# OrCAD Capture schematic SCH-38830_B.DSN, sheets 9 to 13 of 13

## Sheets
9 09 FLEXSPI FLASH: size C
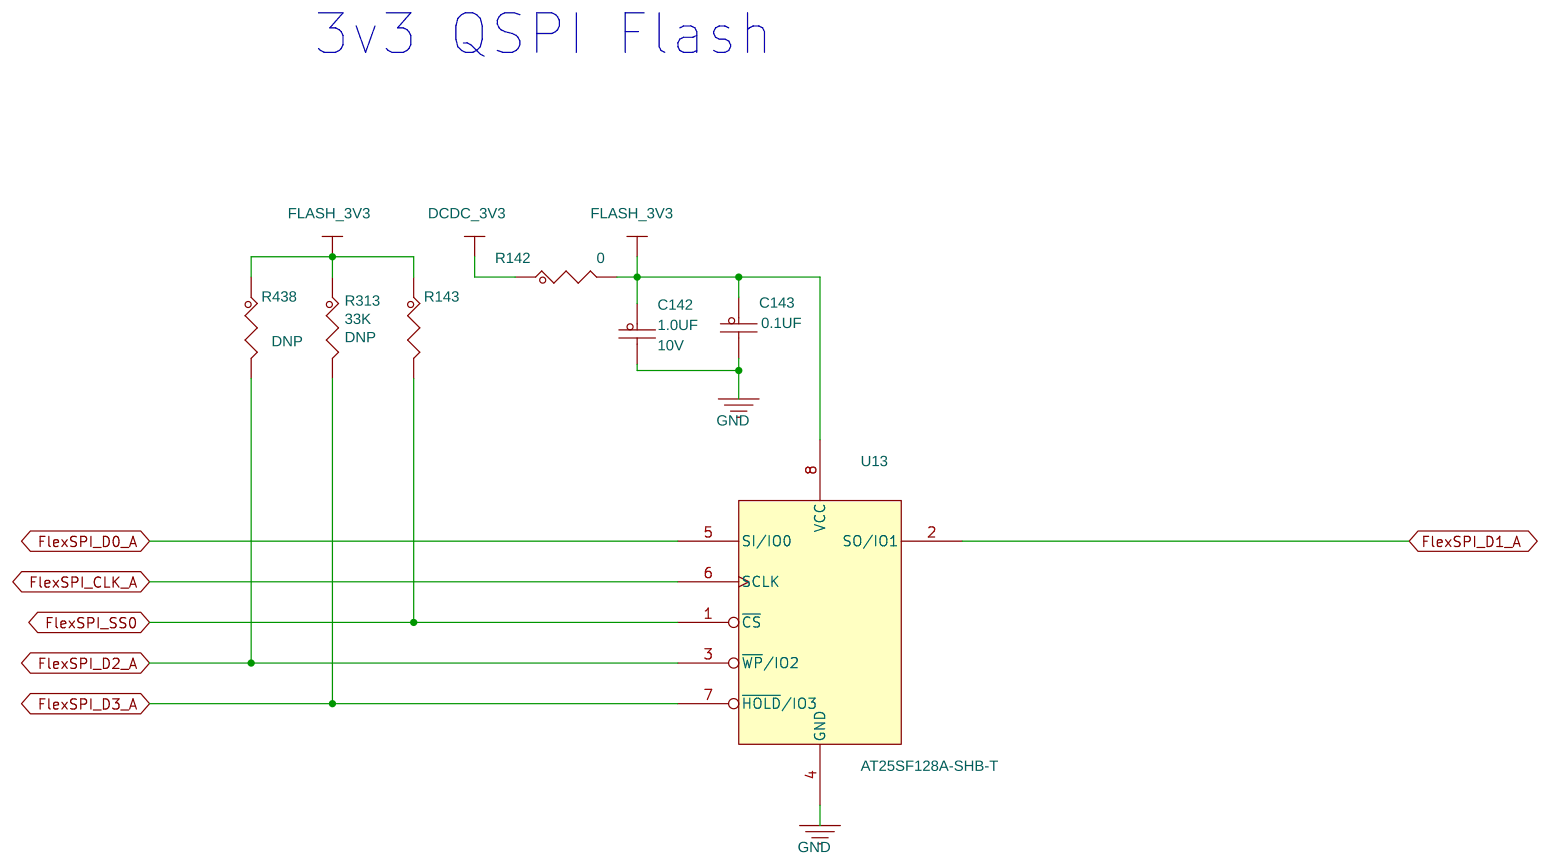
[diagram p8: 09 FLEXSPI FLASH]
10 11 FREELINK: size D; title: MIMXRT1020-EVK
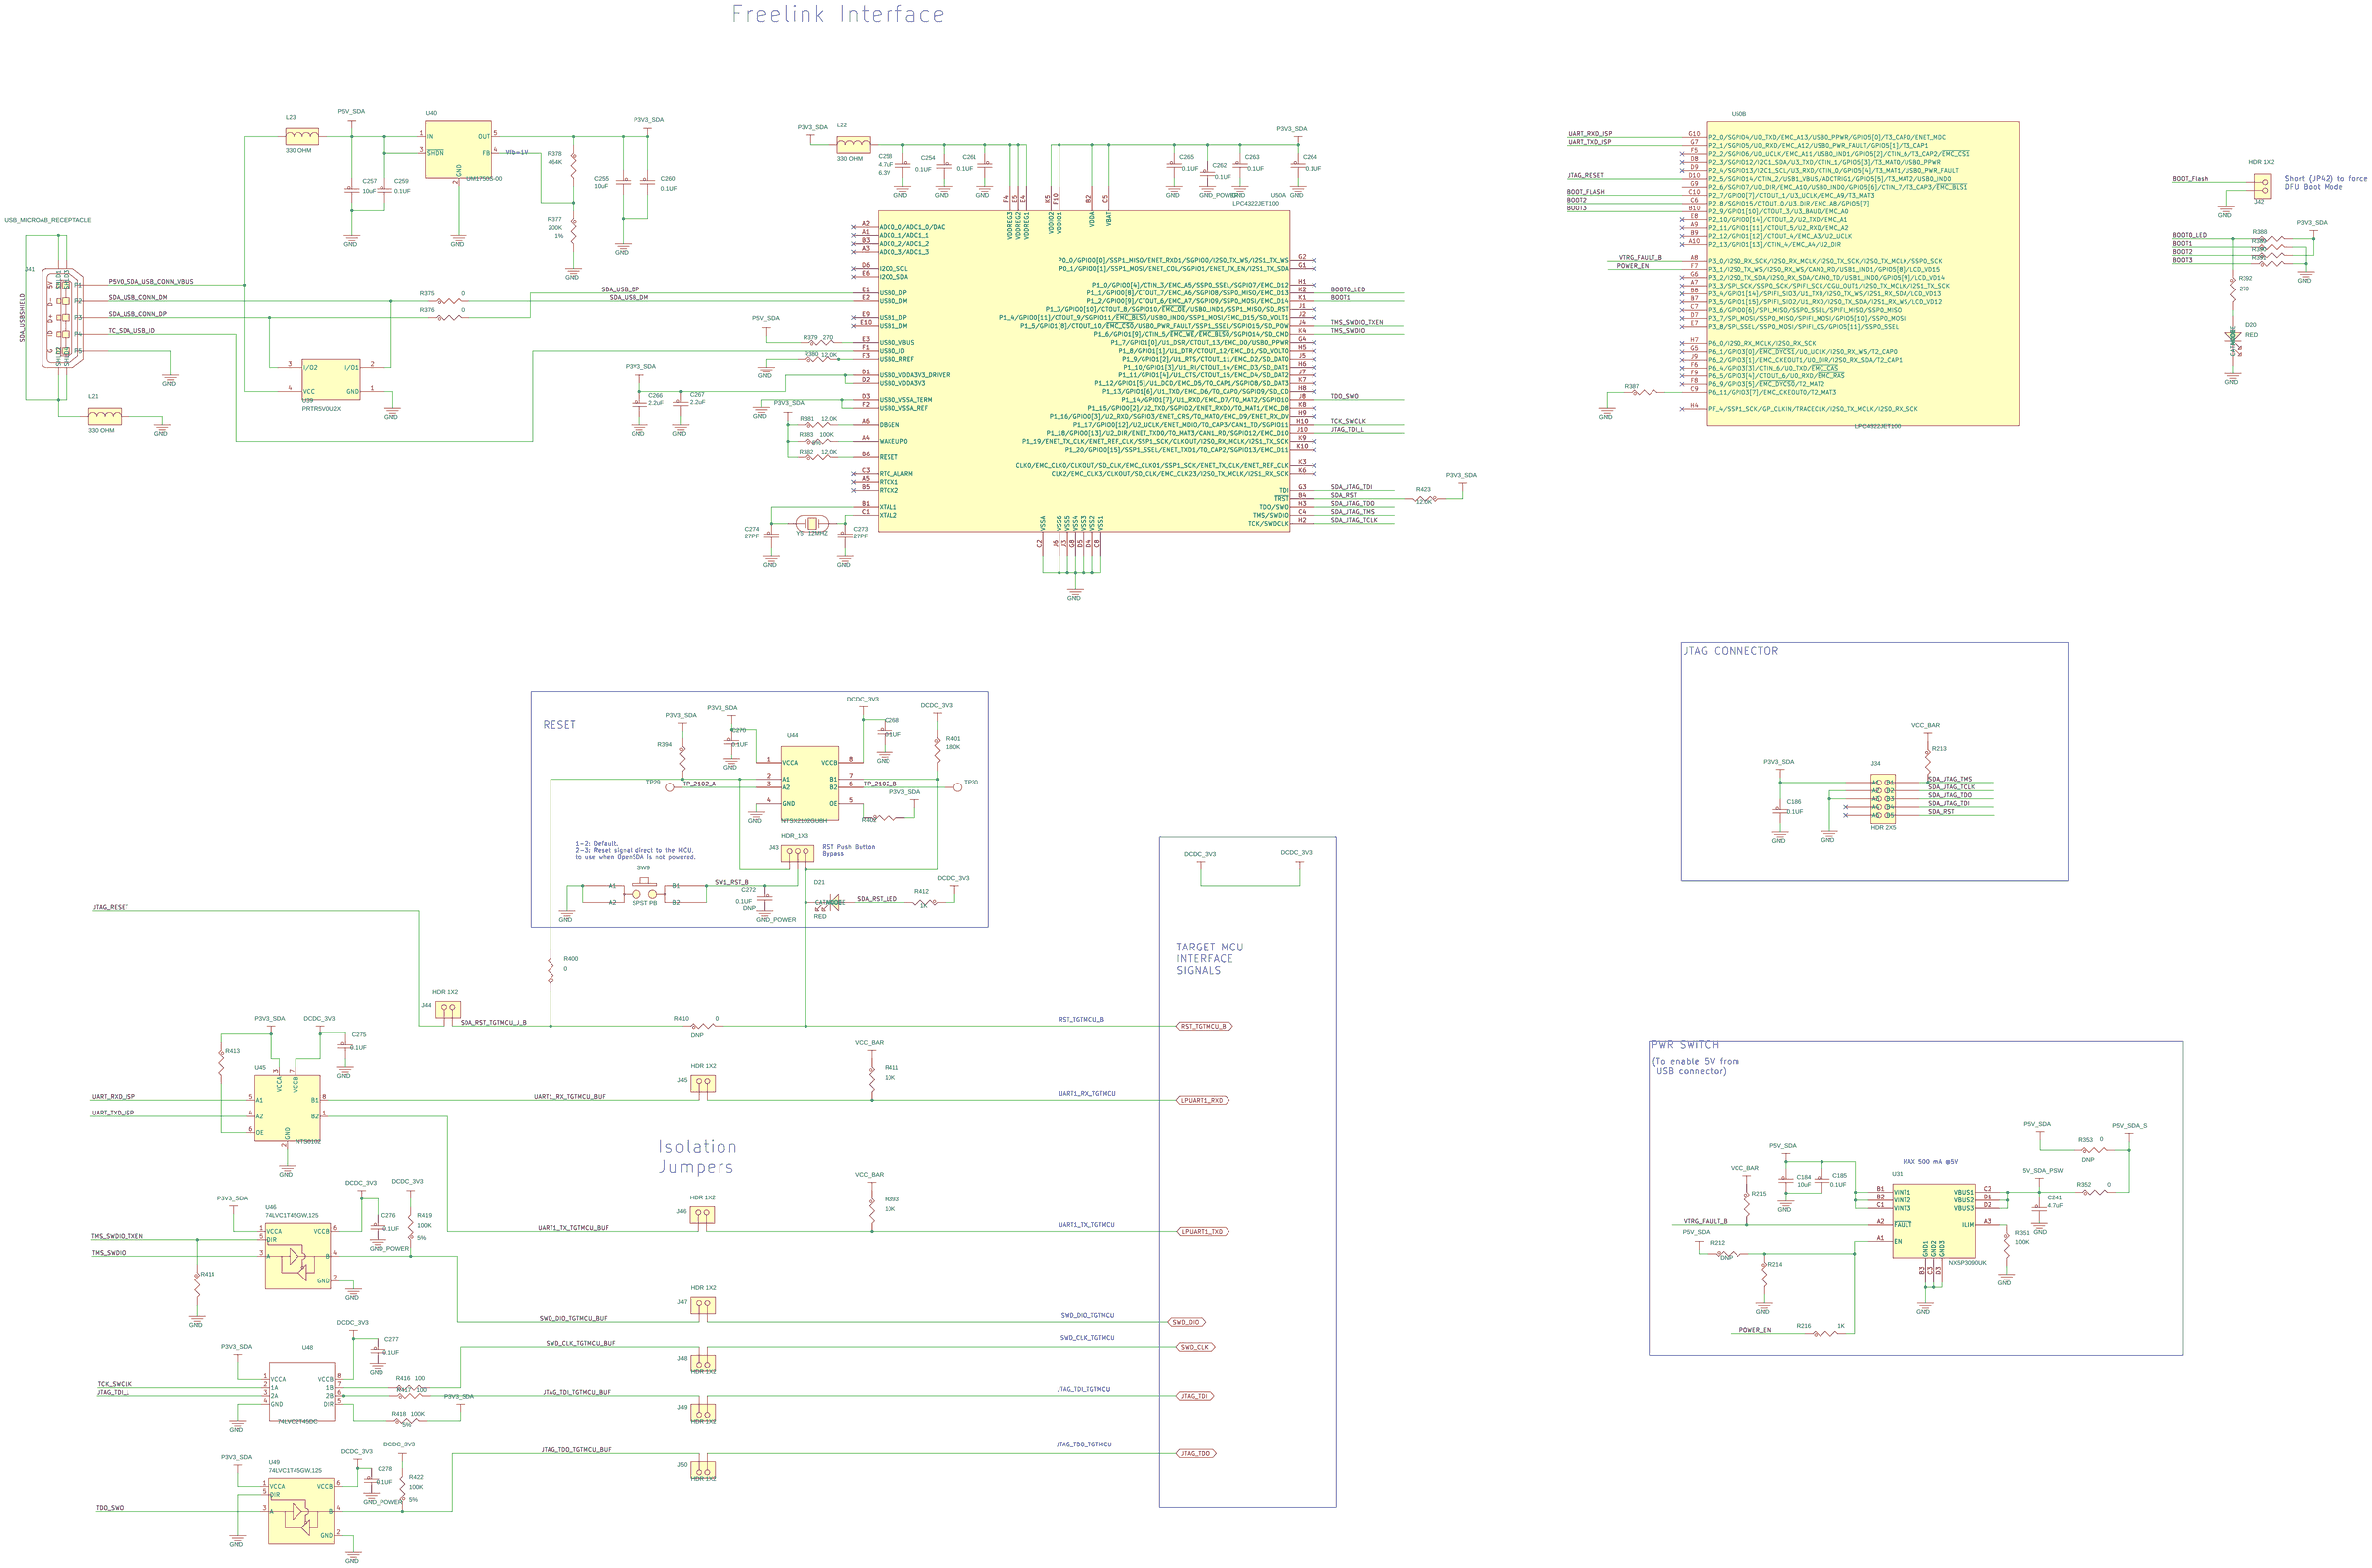
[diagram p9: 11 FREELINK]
11 12 BOOT: size C; title: MIMXRT1020-EVK
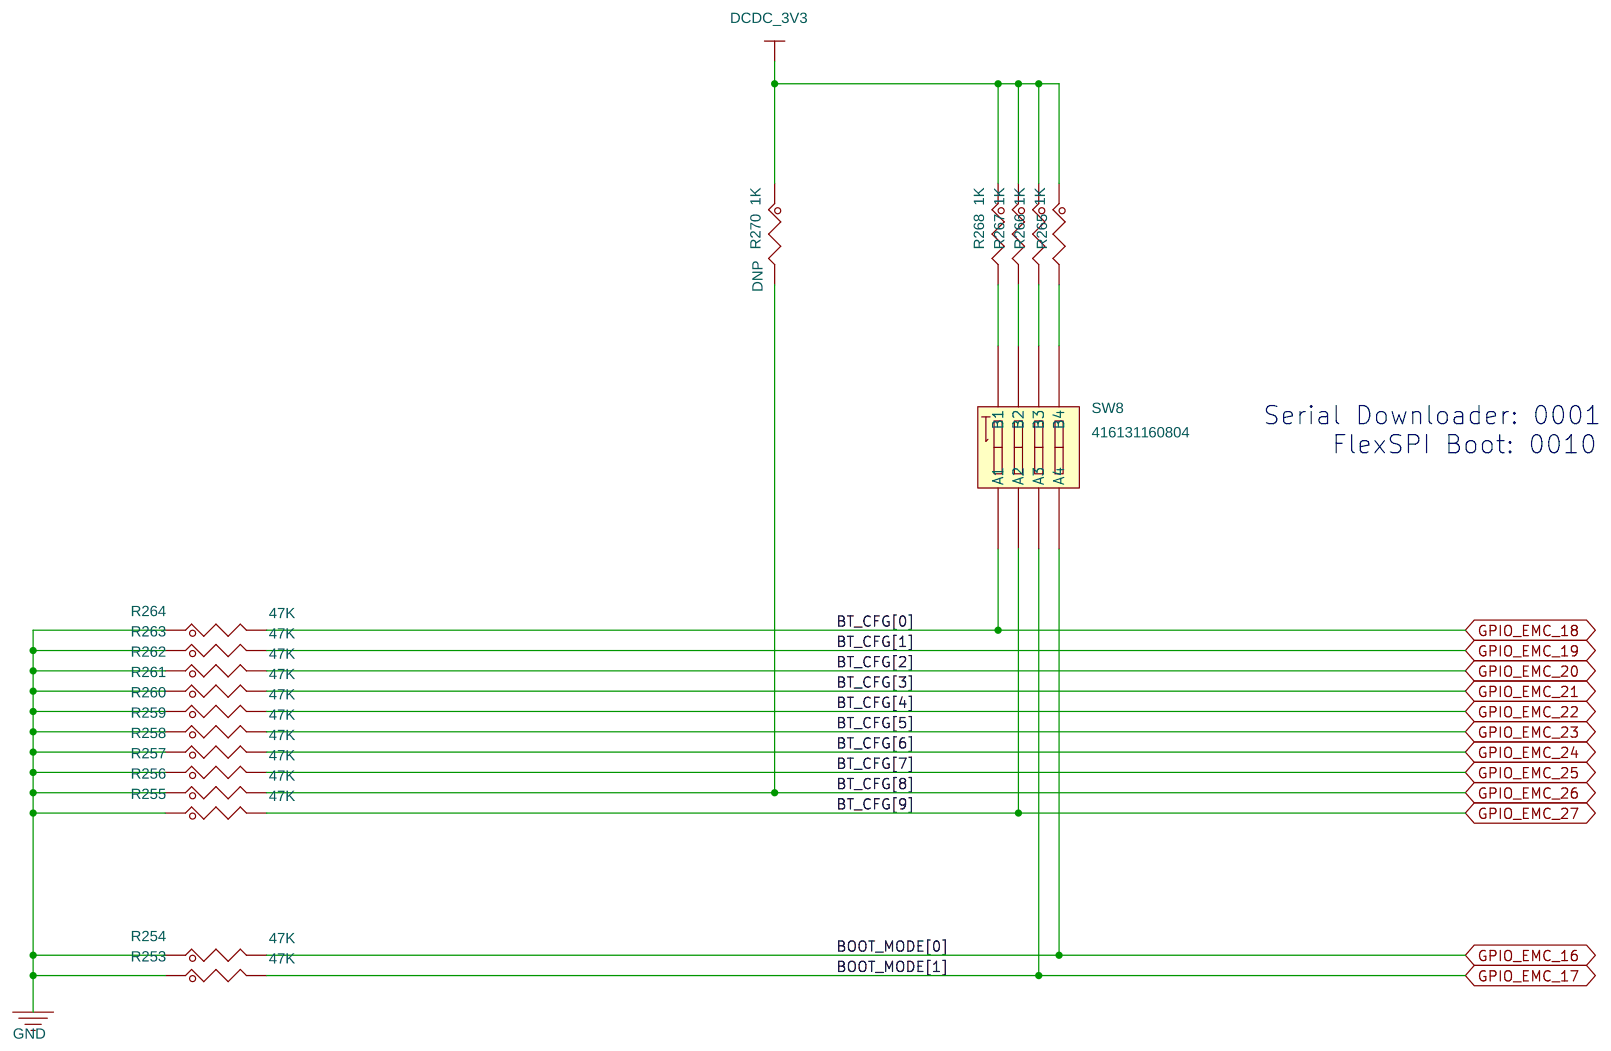
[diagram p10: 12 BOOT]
12 13 MISC: size C; title: MIMXRT1020-EVK
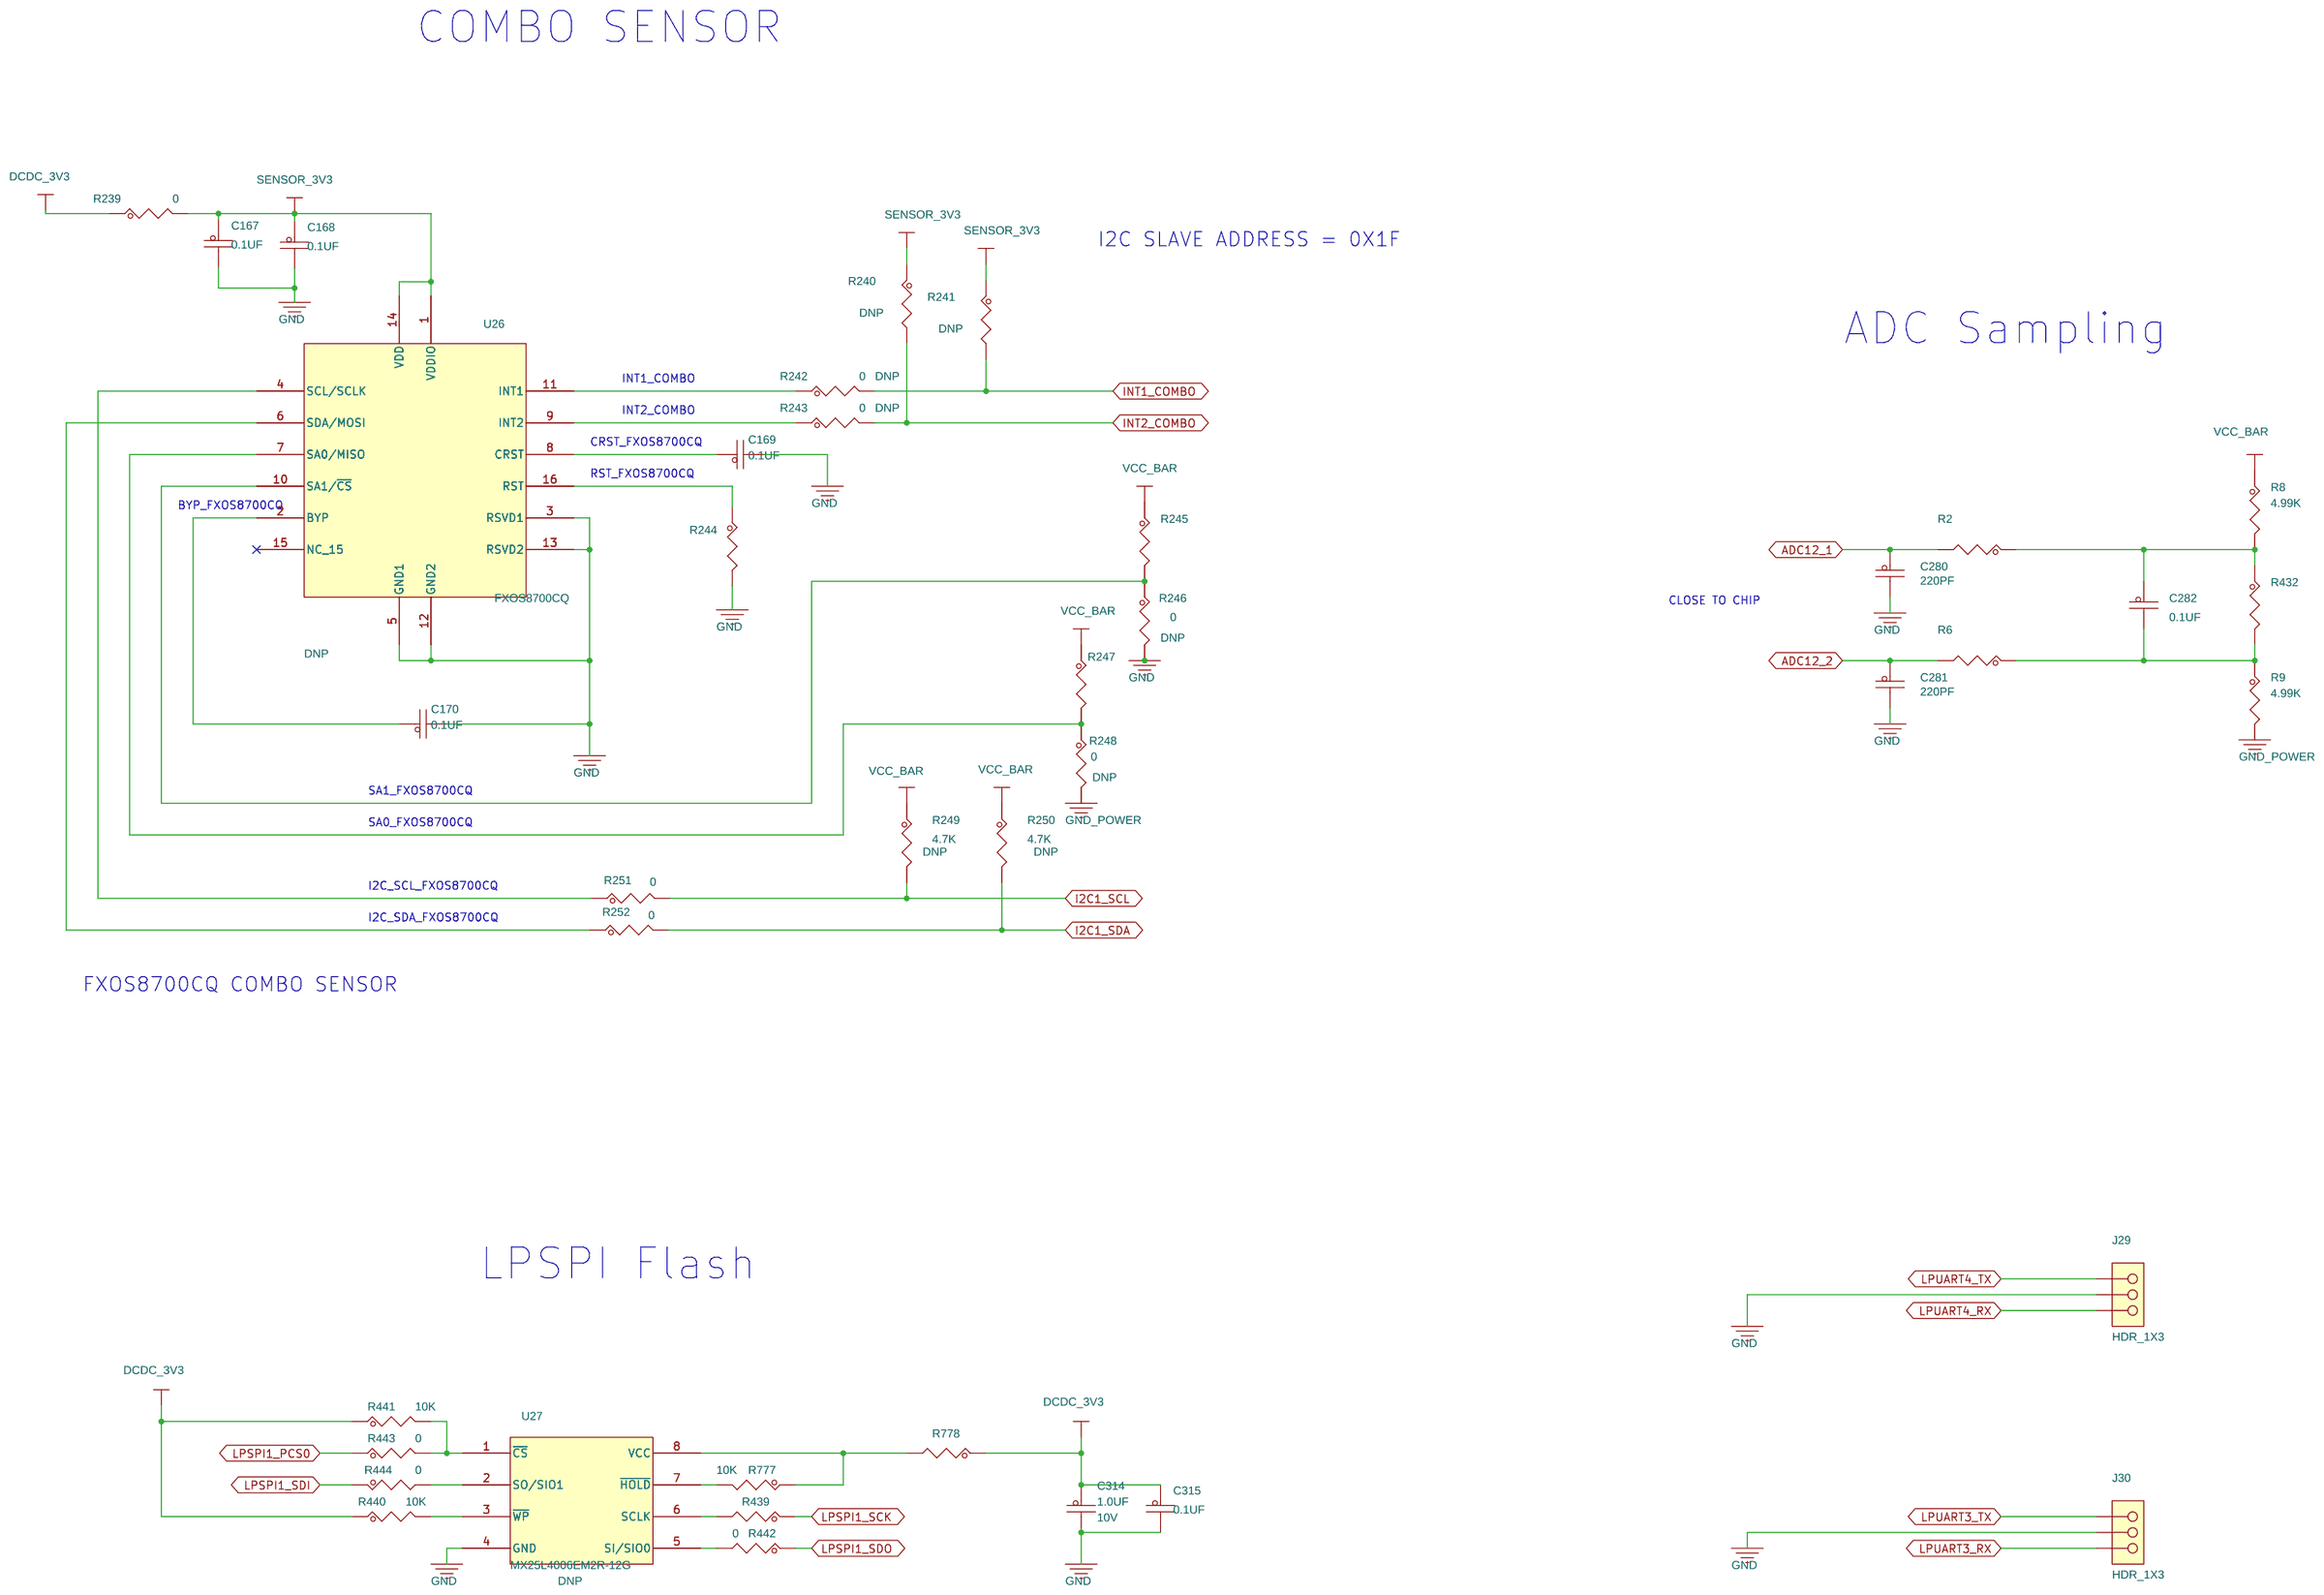
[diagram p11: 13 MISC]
13 10 ARDUINO/JTAG: size C; title: MIMXRT1020-EVK
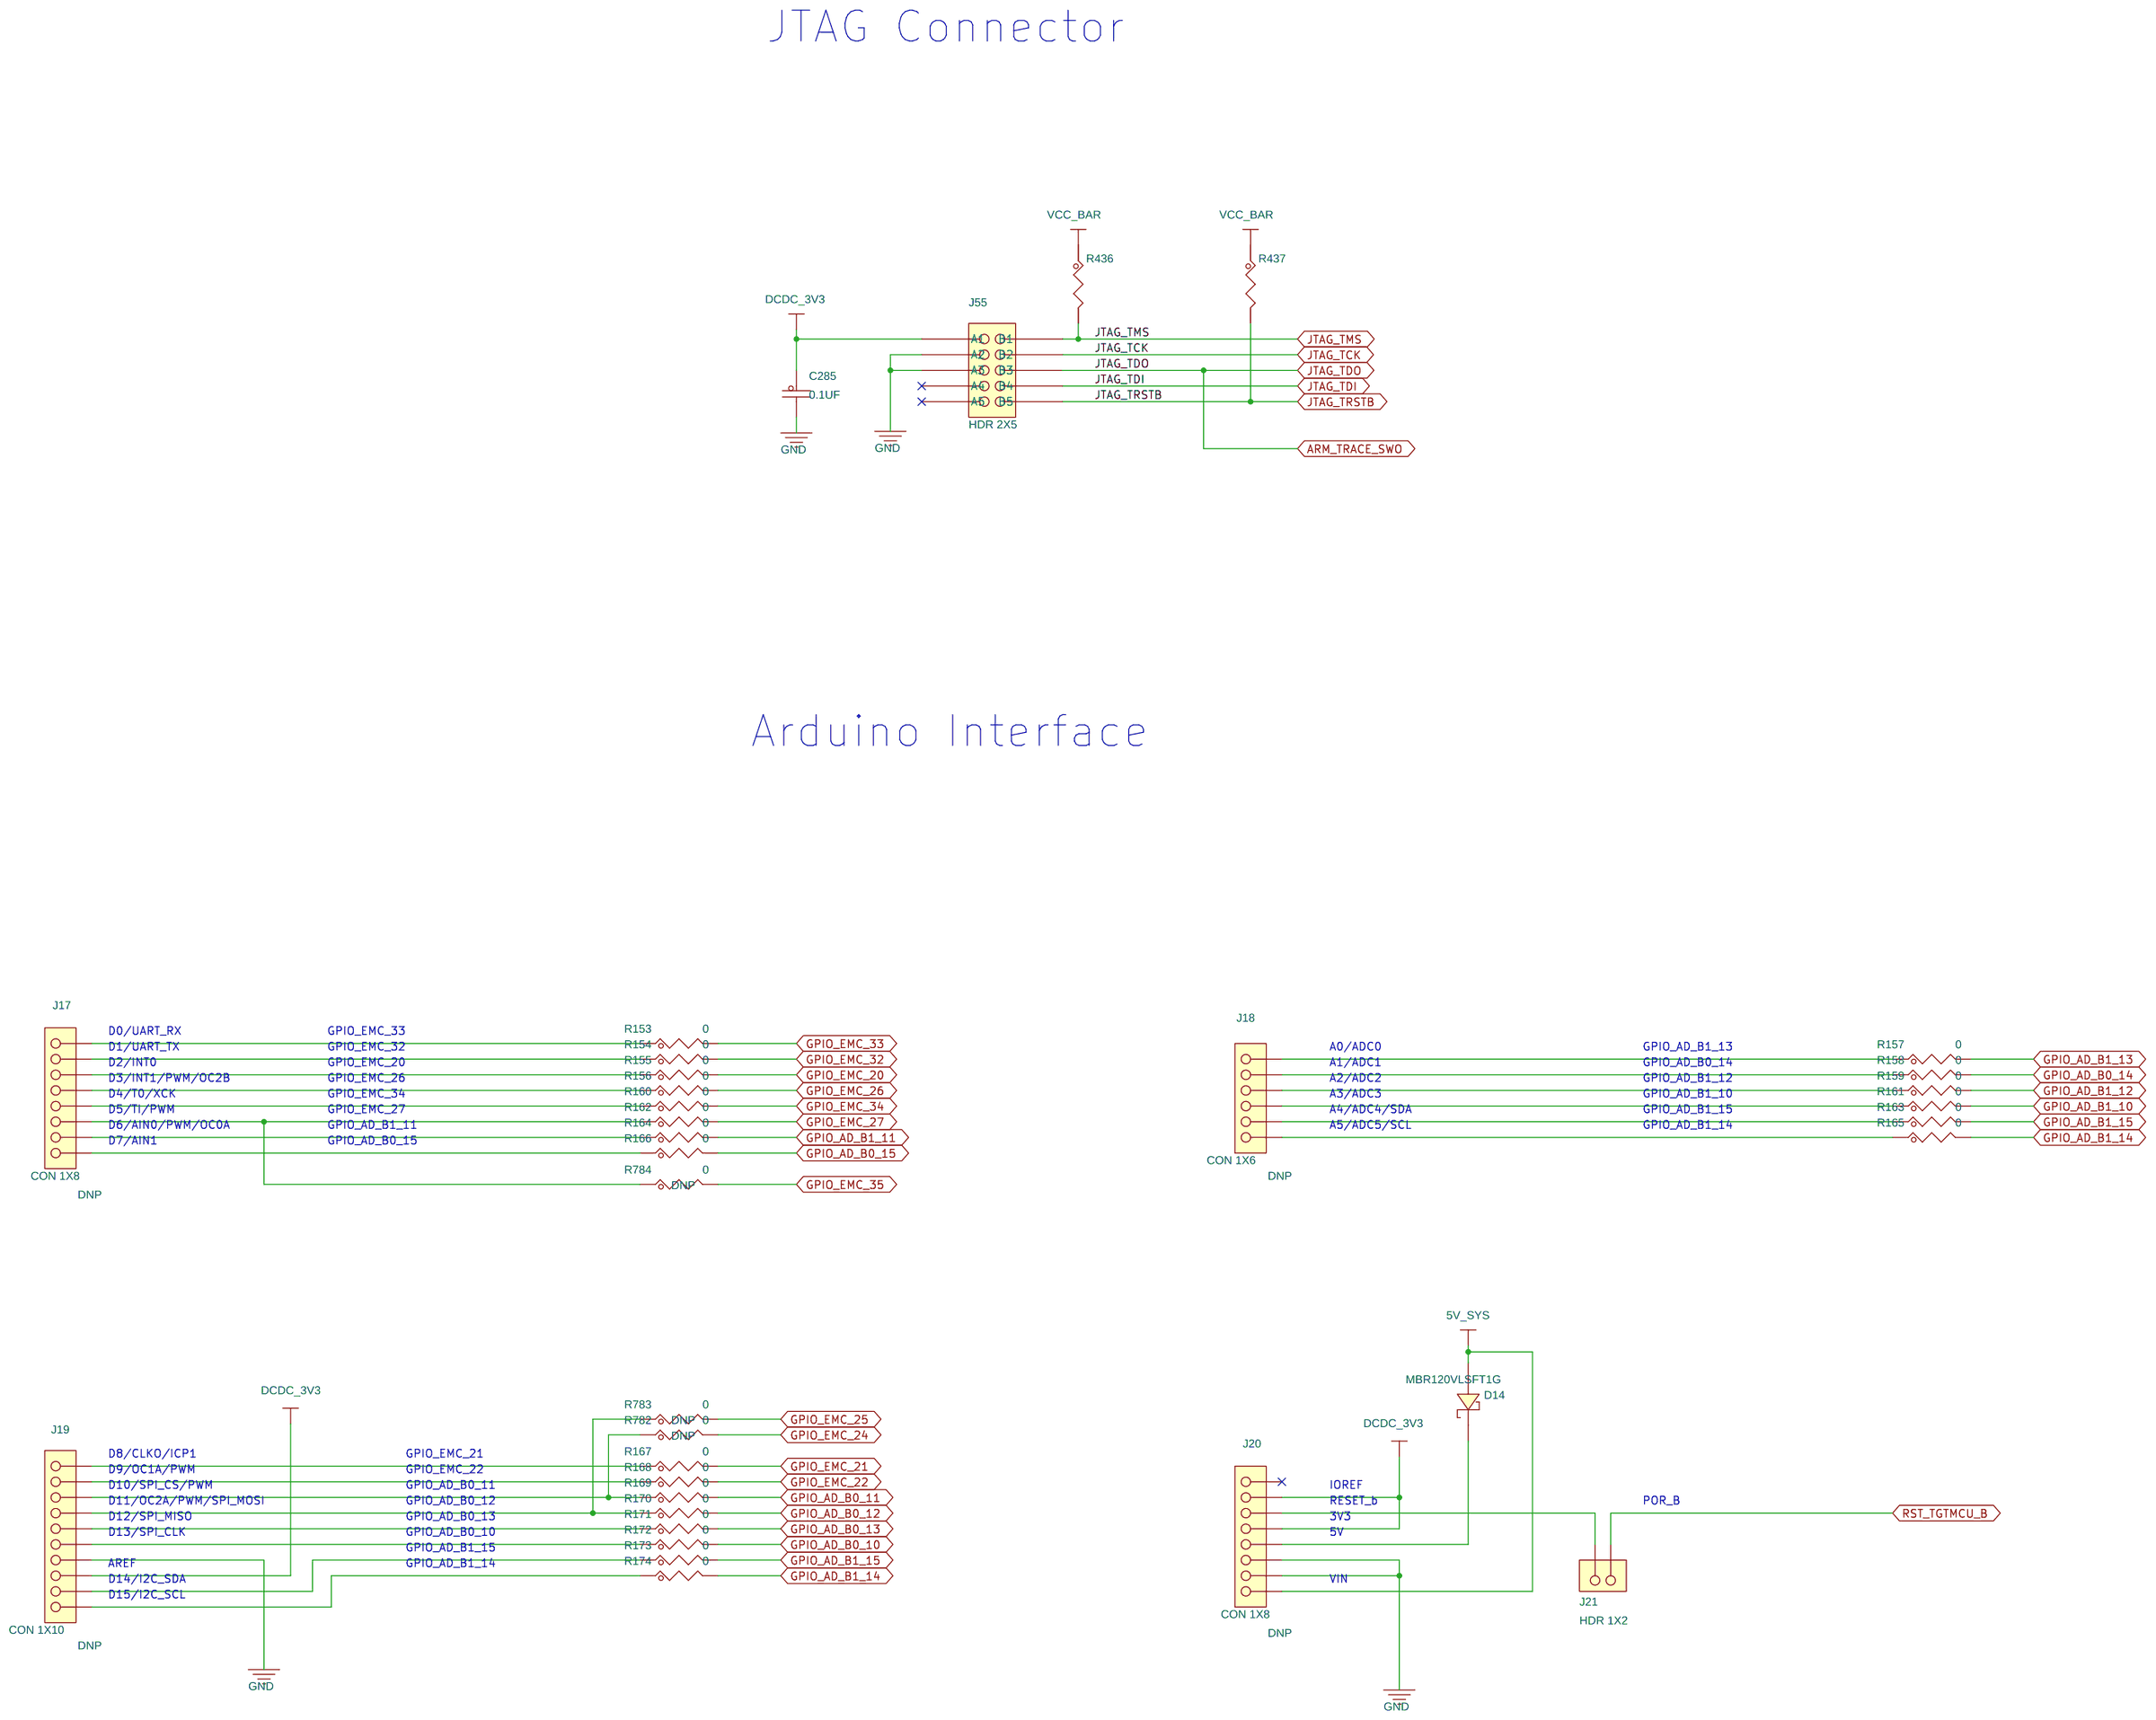
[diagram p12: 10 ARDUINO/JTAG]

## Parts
sheet 09 FLEXSPI FLASH
C142  1.0UF  [0402_CC]
C143  0.1UF  [CC0402_25]
R142  0  [0402_CC]
R143  10K  [0402_CC]
R313  33K  [RC0402_25]
R438  10K  [0402_CC]
U13  AT25SF128A-SHB-T  [SO8-25X75-200]
sheet 10 ARDUINO/JTAG
C285  0.1UF  [CC0402_25]
D14  MBR120VLSFT1G  [SOD-123]
J17  CON 1X8  [con_skt1x8_th]
J18  CON 1X6  [con_skt1x6_th]
J19  CON 1X10  [con_skt1x10_th]
J20  CON 1X8  [con_skt1x8_th]
J21  HDR 1X2  [HDR102]
J55  HDR 2X5  [hdr205_50_th]
R153  0  [0402_CC]
R154  0  [0402_CC]
R155  0  [0402_CC]
R156  0  [0402_CC]
R157  0  [0402_CC]
R158  0  [0402_CC]
R159  0  [0402_CC]
R160  0  [0402_CC]
R161  0  [0402_CC]
R162  0  [0402_CC]
R163  0  [0402_CC]
R164  0  [0402_CC]
R165  0  [0402_CC]
R166  0  [0402_CC]
R167  0  [0402_CC]
R168  0  [0402_CC]
R169  0  [0402_CC]
R170  0  [0402_CC]
R171  0  [0402_CC]
R172  0  [0402_CC]
R173  0  [0402_CC]
R174  0  [0402_CC]
R436  10K  [0402_CC]
R437  10K  [0402_CC]
R782  0  [0402_CC]
R783  0  [0402_CC]
R784  0  [0402_CC]
sheet 11 FREELINK
C184  10uF  [CC0603_OV]
C185  0.1UF  [CC0402_25]
C186  0.1UF  [CC0402_25]
C241  4.7uF  [0402_CC]
C254  0.1UF  [CC0402_25]
C255  10uF  [CC0603_OV]
C257  10uF  [CC0603_OV]
C258  4.7uF  [0402_CC]
C259  0.1UF  [CC0402_25]
C260  0.1UF  [CC0402_25]
C261  0.1UF  [CC0402_25]
C262  0.1UF  [CC0402_25]
C263  0.1UF  [CC0402_25]
C264  0.1UF  [CC0402_25]
C265  0.1UF  [CC0402_25]
C266  2.2uF  [CC0402_25]
C267  2.2uF  [CC0402_25]
C268  0.1UF  [CC0402_25]
C270  0.1UF  [CC0402_25]
C272  0.1UF  [CC0402_25]
C273  27PF  [CC0402_25]
C274  27PF  [CC0402_25]
C275  0.1UF  [CC0402_25]
C276  0.1UF  [CC0402_25]
C277  0.1UF  [CC0402_25]
C278  0.1UF  [CC0402_25]
D20  RED  [LED_0603]
D21  RED  [LED_0603]
J34  HDR 2X5  [hdr205_50_th]
J41  USB_MICROAB_RECEPTACLE  [con_usb5_microab_0p65_sm]
J42  HDR 1X2  [HDR102]
J43  HDR_1X3  [HDR103]
J44  HDR 1X2  [HDR102]
J45  HDR 1X2  [HDR102]
J46  HDR 1X2  [HDR102]
J47  HDR 1X2  [HDR102]
J48  HDR 1X2  [HDR102]
J49  HDR 1X2  [HDR102]
J50  HDR 1X2  [HDR102]
L21  330 OHM  [ind_1608]
L22  330 OHM  [ind_1608]
L23  330 OHM  [ind_1608]
R212  10K  [0402_CC]
R213  10K  [0402_CC]
R214  15K  [RC0402_25]
R215  10K  [0402_CC]
R216  1K  [0402_CC]
R351  100K  [RC0402_25]
R352  0  [0402_CC]
R353  0  [0402_CC]
R375  0  [0402_CC]
R376  0  [0402_CC]
R377  200K  [0402_CC]
R378  464K  [0402_CC]
R379  270  [RC0402_25]
R380  12.0K  [RC0402_25]
R381  12.0K  [RC0402_25]
R382  12.0K  [RC0402_25]
R383  100K  [0402_CC]
R387  2.2K  [RC0402_25]
R388  2.2K  [RC0402_25]
R389  2.2K  [RC0402_25]
R390  2.2K  [RC0402_25]
R391  2.2K  [RC0402_25]
R392  270  [RC0402_25]
R393  10K  [0402_CC]
R394  10K  [0402_CC]
R400  0  [0402_CC]
R401  180K  [RC0402_25]
R402  4.7K  [RC0402_25]
R410  0  [0402_CC]
R411  10K  [0402_CC]
R412  1K  [0402_CC]
R413  4.7K  [RC0402_25]
R414  2.2K  [RC0402_25]
R416  100  [RC0402_25]
R417  100  [RC0402_25]
R418  100K  [0402_CC]
R419  100K  [0402_CC]
R422  100K  [0402_CC]
R423  12.0K  [RC0402_25]
SW9  SPST PB  [SW4_PB_ESW_SM_P177]
TP29  TPAD_030  [TPAD_030]
TP30  TPAD_030  [TPAD_030]
U31  NX5P3090UK  [wlcsp12_0p4_1p38x1p68mm_smdp]
U39  PRTR5V0U2X  [SOT143B]
U40  UM1750S-00  [sot23-5_a]
U44  NTSX2102GU8H  [xqfn8_1p45x1p25mm]
U45  NTS0102  [tssop8_a]
U46  74LVC1T45GW,125  [SOT-363_0P65_SMT]
U48  74LVC2T45DC  [SSOP8_DCU]
U49  74LVC1T45GW,125  [SOT-363_0P65_SMT]
U50  LPC4322JET100  [fbga100_0p8_9x9]  (sections A,B)
Y5  12MHZ  [xtl2_11p6x4p85_sm]
sheet 12 BOOT
R253  47K  [RC0402_25]
R254  47K  [RC0402_25]
R255  47K  [RC0402_25]
R256  47K  [RC0402_25]
R257  47K  [RC0402_25]
R258  47K  [RC0402_25]
R259  47K  [RC0402_25]
R260  47K  [RC0402_25]
R261  47K  [RC0402_25]
R262  47K  [RC0402_25]
R263  47K  [RC0402_25]
R264  47K  [RC0402_25]
R265  1K  [RC0402_25]
R266  1K  [RC0402_25]
R267  1K  [RC0402_25]
R268  1K  [RC0402_25]
R270  1K  [RC0402_25]
SW8  416131160804  [sw4_dip_1p27_6p3x5p7]
sheet 13 MISC
C167  0.1UF  [CC0402_25]
C168  0.1UF  [CC0402_25]
C169  0.1UF  [CC0402_25]
C170  0.1UF  [CC0402_25]
C280  220PF  [CC0402_25]
C281  220PF  [CC0402_25]
C282  0.1UF  [CC0402_25]
C314  1.0UF  [0402_CC]
C315  0.1UF  [0402_CC]
J29  HDR_1X3  [HDR103]
J30  HDR_1X3  [HDR103]
R2  100  [RC0402_25]
R6  100  [RC0402_25]
R8  4.99K  [RC0402_25]
R9  4.99K  [RC0402_25]
R239  0  [0402_CC]
R240  10K  [0402_CC]
R241  10K  [0402_CC]
R242  0  [0402_CC]
R243  0  [0402_CC]
R244  10K  [0402_CC]
R245  10K  [0402_CC]
R246  0  [0402_CC]
R247  10K  [0402_CC]
R248  0  [0402_CC]
R249  4.7K  [RC0402_25]
R250  4.7K  [RC0402_25]
R251  0  [0402_CC]
R252  0  [0402_CC]
R432  10K  [0402_CC]
R439  0  [0402_CC]
R440  10K  [0402_CC]
R441  10K  [0402_CC]
R442  0  [0402_CC]
R443  0  [0402_CC]
R444  0  [0402_CC]
R777  10K  [0402_CC]
R778  0  [0402_CC]
U26  FXOS8700CQ  [QFN5X3_0P5_3X3]
U27  MX25L4006EM2R-12G  [SO8-25X75-200]

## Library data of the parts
C142 C314 = CAP_NP: CAP CER 1.0UF 10V 10% X5R 0402; AGILE_PN: 150-75772; CAD_APPROVED: Yes; FPLIST: CC0402_25,CC0402_HD,0402_CC; HEIGHT: 0.6MM; MFG_NAME01: YAGEO AMERICA; MFG_PN01: CC0402KRX5R6BB105; ROHS: Yes; VOLTAGE: 10V; voltage rating: 10V
C143 C167-C170 C185 C186 C254 C259-C265 C268 C270 C275-C278 C282 C285 C315 = CAP_NP: CAP CER 0.1UF 10V 10% X5R 0402; AGILE_PN: 150-75634; CAD_APPROVED: Yes; FPLIST: CC0402_25,CC0402_HD,0402_CC; HEIGHT: 0.64MM; MFG_NAME01: YAGEO AMERICA; MFG_PN01: CC0402KRX5R6BB104; ROHS: Yes; Tolerance: 10%; VOLTAGE: 10V
R142 R153-R174 R239 R251 R252 R352 R375 R376 R400 R439 R442-R444 R778 = RES: RES MF ZERO OHM 1/16W 5% 0402; AGILE_PN: 470-75394; CAD_APPROVED: Yes; FPLIST: RC0402_25,RC0402_HD,RC0402_X2,0402_CC; HEIGHT: 0.45 MM; MFG_NAME01: ROHM; MFG_PN01: MCR01MZPJ000; ROHS: Yes; Tolerance: 5%
R143 R213 R215 R394 R436 R437 = RES: RES MF 10K 1/16W 5% 0402; AGILE_PN: 470-75557; CAD_APPROVED: Yes; FPLIST: RC0402_25,RC0402_HD,0402_CC; HEIGHT: 0.4 MM; MFG_NAME01: VISHAY INTERTECHNOLOGY; MFG_PN01: CRCW040210K0JNED; ROHS: Yes; TOL: 5%; Tolerance: 5%
R313 = RES: RES MF 33K  1/16W 1% 0402; AGILE_PN: 470-31004; ASSY_OPT: DNP; CAD_APPROVED: Yes; FPLIST: RC0402_25,RC0402_HD,0402_CC; HEIGHT: 0.40 MM; MFG_NAME01: YAGEO AMERICA; MFG_PN01: RC0402FR-0733KL; ROHS: Yes; Temp_Range: -55°C ~ 155°C; Tolerance: 1%
R438 = RES: RES MF 10K 1/16W 5% 0402; AGILE_PN: 470-75557; ASSY_OPT: DNP; CAD_APPROVED: Yes; FPLIST: RC0402_25,RC0402_HD,0402_CC; HEIGHT: 0.4 MM; MFG_NAME01: VISHAY INTERTECHNOLOGY; MFG_PN01: CRCW040210K0JNED; ROHS: Yes; TOL: 5%; Tolerance: 5%
U13 = AT25SF128A: IC MEM NOR FLASH DUAL/QUAD SPI 128MBIT 133MHZ 2.7-3.6V SOP8; AGILE_PN: TMP-WF-34467; CAD_APPROVED: Yes; HEIGHT: 2.16MM; MFG_NAME01: Adesto Technologies Corporation, Inc; PRE_APN: 342-00805; ROHS: Yes; Temp_Range: -40°C ~ 85°C
D14 = DIODE_SCHTKY: DIODE SCH RECT 1A 20V SMT; AGILE_PN: 480-75997; CAD_APPROVED: Yes; HEIGHT: 1MM; MFG_NAME01: ON SEMICONDUCTOR; ROHS: Yes
J17 J20 = CONN_HDR_8X1: CON 1X8 SKT TH 100MIL SP 343H AU 392L; AGILE_PN: 210-80963; ASSY_OPT: DNP; CAD_APPROVED: Yes; HEIGHT: 8.7MM; MFG_NAME01: Townes Enterprice Co.,Ltd; MFG_PN01: F209-1*08SG1-0A-NH; ROHS: Yes
J18 = CONN_HDR_6X1: CON 1X6 SKT TH 100MIL SP 343H AU 392L; AGILE_PN: 210-80962; ASSY_OPT: DNP; CAD_APPROVED: Yes; HEIGHT: 8.7MM; MFG_NAME01: Townes Enterprice Co.,Ltd; MFG_PN01: F209-1*06SG1-0A-NH; ROHS: Yes
J19 = CONN_HDR_10X1: CON 1X10 SKT TH 100MIL SP 343H AU 392L; AGILE_PN: 210-80964; ASSY_OPT: DNP; CAD_APPROVED: Yes; HEIGHT: 8.7MM; MFG_NAME01: Townes Enterprice Co.,Ltd; MFG_PN01: F209-1*10SG1-0A-NH; ROHS: Yes
J21 J42 J44-J50 = CONN_HDR_2X1: HDR 1X2 TH 100MIL SP 339H AU 98L; AGILE_PN: 210-81490; CAD_APPROVED: Yes; HEIGHT: 8.59MM; MFG_NAME01: ANYTRONIC CORPORATION LIMITED; MFG_PN01: 0901S0202011N9T-31RF; ROHS: Yes; Temp_Range: -55°C to +105°C
J34 J55 = CONN_HDR_5X2: HDR 2X5 TH 50MIL CTR 172H AU 91L; AGILE_PN: 210-81466; CAD_APPROVED: Yes; HEIGHT: 4.38MM; MFG_NAME01: ANYTRONIC CORPORATION LIMITED; MFG_PN01: 0922S0205011N9T-31RF; ROHS: Yes; Temp_Range: -55DegC to +105DegC
R242 R243 R246 R248 R353 R410 R782-R784 = RES: RES MF ZERO OHM 1/16W 5% 0402; AGILE_PN: 470-75394; ASSY_OPT: DNP; CAD_APPROVED: Yes; FPLIST: RC0402_25,RC0402_HD,RC0402_X2,0402_CC; HEIGHT: 0.45 MM; MFG_NAME01: ROHM; MFG_PN01: MCR01MZPJ000; ROHS: Yes; Tolerance: 5%
C184 C255 C257 = CAP_NP: CAP CER 10UF 10V 10% X5R 0603; AGILE_PN: 150-78675; CAD_APPROVED: Yes; FPLIST: CC0603_OV,CC0603,0603_CC; HEIGHT: 1.016MM; MFG_NAME01: MURATA; MFG_PN01: GRM188R61A106KE69D; ROHS: Yes; Temp_Range: -55°C ~ 85°C; Tolerance: 10%; VOLTAGE: 10v
C241 = CAP_NP: CAP CER 4.7UF 6.3V 20% X5R 0402; AGILE_PN: 150-78463; CAD_APPROVED: Yes; FPLIST: CC0402_25,CC0402_HD,0402_CC; HEIGHT: 0.65MM; MFG_NAME01: TDK; MFG_PN01: C1005X5R0J475M050BC; ROHS: Yes; TOL: 20%; Tolerance: 20%; VOLTAGE: 6.3V
C258 = CAP_NP: CAP CER 4.7UF 6.3V 20% X5R 0402; AGILE_PN: 150-78463; CAD_APPROVED: Yes; FPLIST: CC0402_25,CC0402_HD,0402_CC; HEIGHT: 0.65MM; MFG_NAME01: TDK; MFG_PN01: C1005X5R0J475M050BC; ROHS: Yes; Tolerance: 20%; VOLTAGE: 6.3V; voltage rating: 6.3V
C266 C267 = CAP_NP: CAP CER 2.2uF 6.3V 10% X5R 0402; AGILE_PN: 150-79454; CAD_APPROVED: Yes; FPLIST: CC0402_25,CC0402_HD,0402_CC; HEIGHT: 0.55MM; MFG_NAME01: MURATA; MFG_PN01: GRM155R60J225KE95; ROHS: Yes; Tolerance: 10%; VOLTAGE: 6.3V
C272 = CAP_NP: CAP CER 0.1UF 10V 10% X5R 0402; AGILE_PN: 150-75634; ASSY_OPT: DNP; CAD_APPROVED: Yes; FPLIST: CC0402_25,CC0402_HD,0402_CC; HEIGHT: 0.64MM; MFG_NAME01: YAGEO AMERICA; MFG_PN01: CC0402KRX5R6BB104; ROHS: Yes; Tolerance: 10%; VOLTAGE: 10V
C273 C274 = CAP_NP: CAP CER 27PF 50V 5% C0G 0402; AGILE_PN: 150-30109; CAD_APPROVED: Yes; FPLIST: CC0402_25,CC0402_HD,0402_CC; HEIGHT: .55mm; MFG_NAME01: KEMET; MFG_PN01: C0402C270J5GAC; ROHS: Yes; Tolerance: 5%; VOLTAGE: 50V
D20 D21 = LED: LED ULTRA BRIGHT RED SGL 30MA 0603; AGILE_PN: 370-75079; CAD_APPROVED: Yes; HEIGHT: 0.9MM; MFG_NAME01: LITE ON; MFG_PN01: LTST-C190KRKT; ROHS: Yes
J41 = USB_MINI_AB_RECEPTACLE: CON 5 USB MICRO_AB RA SKT SMT 0.65MM SP 110H AU; AGILE_PN: 211-80104; CAD_APPROVED: Yes; HEIGHT: 2.8MM; MFG_NAME01: ANYTRONIC CORPORATION LIMITED; MFG_PN01: 23971101#LCP-58RF; ROHS: Yes; Temp_Range: -55&#8451; to 105&#8451;
J29 J30 J43 = CONN_HDR_3X1: HDR 1X3 TH 100MIL SP 338H AU 98L; AGILE_PN: 210-81491; CAD_APPROVED: Yes; HEIGHT: 8.59MM; MFG_NAME01: ANYTRONIC CORPORATION LIMITED; MFG_PN01: 0901S0203011N9T-31RF; ROHS: Yes; Temp_Range: -55°C to +105°C
L21-L23 = BEAD: IND FER BEAD 330OHM@100MHZ 1.7A 0603; AGILE_PN: 180-78156; CAD_APPROVED: Yes; FPLIST: ind_1608,0603_CC; HEIGHT: 0.95MM; MFG_NAME01: TDK; MFG_PN01: MPZ1608S331A; PART_TYPE: FERRITE\BEAD; ROHS: Yes; Tolerance: 25%
R212 R240 R241 = RES: RES MF 10K 1/16W 5% 0402; AGILE_PN: 470-75557; ASSY_OPT: DNP; CAD_APPROVED: Yes; FPLIST: RC0402_25,RC0402_HD,0402_CC; HEIGHT: 0.4 MM; MFG_NAME01: VISHAY INTERTECHNOLOGY; MFG_PN01: CRCW040210K0JNED; ROHS: Yes; Tolerance: 5%
R214 = RES: RES MF 15K  1/16W 1% 0402; AGILE_PN: 470-30965; CAD_APPROVED: Yes; FPLIST: RC0402_25,RC0402_HD,0402_CC; HEIGHT: 0.40 MM; MFG_NAME01: WALSIN TECHNOLOGY CORP.; MFG_PN01: WR04X1502FTL; ROHS: Yes; SIGNAL_MODEL: DEFAULT_RESISTOR_15000OHM_2_1; TOL: 1%; Tolerance: 1%
R216 R265-R268 R412 = RES: RES MF 1.0K 1/16W 5% 0402; AGILE_PN: 470-75555; CAD_APPROVED: Yes; FPLIST: RC0402_25,RC0402_HD,RC0402_X2,0402_CC; HEIGHT: 0.41mm; MFG_NAME01: VISHAY INTERTECHNOLOGY; MFG_PN01: CRCW04021K00JNED; ROHS: Yes; Tolerance: 5%
R351 = RES: RES MF 100K 1/16W 1% 0402; AGILE_PN: 470-76240; CAD_APPROVED: Yes; FPLIST: RC0402_25,RC0402_HD,0402_CC; HEIGHT: 0.4MM; MFG_NAME01: NIC COMPONENTS CORP; MFG_PN01: NRCL04F1003TRF; ROHS: Yes; Tolerance: 1%
R377 = RES: RES MF 200K 1/10W 1% AEC-Q200 0402; AGILE_PN: 470-31093; CAD_APPROVED: Yes; FPLIST: RC0402_25,RC0402_HD,0402_CC; HEIGHT: 0.40 MM; MFG_NAME01: KOA SPEER; MFG_PN01: RK73H1ETTP2003F; ROHS: Yes; Temp_Range: -55C to +155C; Tolerance: 1%
R378 = RES: RES MF 464K 1/10W 1% AEC-Q200 0402; AGILE_PN: 470-31135; CAD_APPROVED: Yes; FPLIST: RC0402_25,RC0402_HD,0402_CC; HEIGHT: 0.40 MM; MFG_NAME01: KOA SPEER; MFG_PN01: RK73H1ETTP4643F; ROHS: Yes; Temp_Range: -55C to +155C; Tolerance: 1%
R379 R392 = RES: RES MF 270 OHM 1/16W 5% 0402; AGILE_PN: 470-81890; CAD_APPROVED: Yes; FPLIST: RC0402_25,RC0402_HD,0402_CC; HEIGHT: 0.4MM; MFG_NAME01: Yageo; MFG_PN01: RC0402JR-07270RL; ROHS: Yes; Temp_Range: -55C to +155C; Tolerance: 5%
R380-R382 R423 = RES: RES MF 12.0K 1/16W 1% 0402; AGILE_PN: 470-76083; CAD_APPROVED: Yes; FPLIST: RC0402_25,RC0402_HD,0402_CC; HEIGHT: 0.4 MM; MFG_NAME01: BOURNS; MFG_PN01: CR0402-FX-1202GLF; ROHS: Yes; Tolerance: 1%
R383 R418 R419 R422 = RES: RES MF 100K 1/16W 5% 0402; AGILE_PN: 470-75597; CAD_APPROVED: Yes; FPLIST: RC0402_25,RC0402_HD,0402_CC; HEIGHT: 0.40 MM; MFG_NAME01: VENKEL COMPANY; MFG_PN01: CR0402-16W-104JT; ROHS: Yes; TOL: 5%; Temp_Range: -55C to +155C; Tolerance: 5%
R387-R391 R414 = RES: RES MF 2.2K 1/16W 5% 0402; AGILE_PN: 470-76602; CAD_APPROVED: Yes; FPLIST: RC0402_25,RC0402_HD,0402_CC; HEIGHT: 0.4 MM; MFG_NAME01: YAGEO AMERICA; MFG_PN01: RC0402JR-072K2L; ROHS: Yes; TOL: 5%; Tolerance: 5%
R244 R245 R247 R393 R411 R432 R440 R441 R777 = RES: RES MF 10K 1/16W 5% 0402; AGILE_PN: 470-75557; CAD_APPROVED: Yes; FPLIST: RC0402_25,RC0402_HD,0402_CC; HEIGHT: 0.4 MM; MFG_NAME01: VISHAY INTERTECHNOLOGY; MFG_PN01: CRCW040210K0JNED; ROHS: Yes; Tolerance: 5%
R401 = RES: RES MF 180K 1/10W 1% AEC-Q200 0402; AGILE_PN: 470-31088; CAD_APPROVED: Yes; FPLIST: RC0402_25,RC0402_HD,0402_CC; HEIGHT: 0.40 MM; MFG_NAME01: KOA SPEER; MFG_PN01: RK73H1ETTP1803F; ROHS: Yes; SIGNAL_MODEL: DEFAULT_RESISTOR_180000OHM_2_1; TOL: 1%; Temp_Range: -55C to +155C; Tolerance: 1%
R402 R413 = RES: RES MF 4.7K 1/16W 5% 0402; AGILE_PN: 470-75626; CAD_APPROVED: Yes; FPLIST: RC0402_25,RC0402_HD,0402_CC; HEIGHT: 0.41mm; MFG_NAME01: NIC COMPONENTS CORP; MFG_PN01: NRCL04J472TRF; ROHS: Yes; SIGNAL_MODEL: DEFAULT_RESISTOR_4700OHM_2_1; TOL: 5%; Tolerance: 5%
R416 R417 = RES: RES MF 100 OHM 1/16W 5% 0402; AGILE_PN: 470-82143; CAD_APPROVED: Yes; FPLIST: RC0402_25,RC0402_HD,RC0402_X2,0402_CC; HEIGHT: 0.45MM; MFG_NAME01: YAGEO AMERICA; MFG_PN01: RC0402JR-07100RL; ROHS: Yes; Temp_Range: -55°C to +155°C; Tolerance: 5%
SW9 = SW_PB_ESW: SW SPST MOM NO PB TACT 50mA 50V SMT; AGILE_PN: 510-77562; CAD_APPROVED: Yes; HEIGHT: 5MM; MFG_NAME01: E SWITCH; MFG_PN01: TL3301AF260QG/TR; ROHS: Yes
TP29 TP30 = TESTLOOP: TEST POINT PAD 30MIL DIA SMT, NO PART TO ORDER; AGILE_PN: 211-76642; CAD_APPROVED: Yes; HEIGHT: 0.1MM; MFG_NAME01: NOTACOMPONENT; MFG_PN01: NOTACOMPONENT; ROHS: Yes
U31 = NX5P3090UK_WLCSP12: IC USB PD TYPE C CURRENT LIMITED PWR SW 2.5-5.5V WLCSP12; AGILE_PN: 312-81574; CAD_APPROVED: Yes; HEIGHT: 0.565 MM; MFG_NAME01: NXP SEMICONDUCTORS; MFG_PN01: NX5P3090UK,012; ROHS: Yes
U39 = PRTR5V0U2X: IC USB ESD PROTECTION 8KV SOT143; AGILE_PN: 315-76725; CAD_APPROVED: Yes; HEIGHT: 1.1MM; MFG_NAME01: NEXPERIA; MFG_PN01: PRTR5V0U2X,215; ROHS: Yes; Temp_Range: -40° C to +85° C
U40 = UM1750S-00_5P: IC VREG LDO ADJ 1-5V 350mA 2.5-6V SOT23-5; AGILE_PN: 315-80554; CAD_APPROVED: Yes; HEIGHT: 1.25MM; MFG_NAME01: Union Semiconductor, Inc; ROHS: Yes
U44 = NTSX2102GU8H_8P: IC DUAL SUPPLY XCVR 50 MBPS 5.5V XQFN8; AGILE_PN: 312-80763; CAD_APPROVED: Yes; HEIGHT: 0.5MM; MFG_NAME01: NXP Semiconductors; ROHS: Yes; VOLTAGE: 5.5V
U45 = NTB0102_8P: IC XCVR 2-BIT 1.65-3.6V/2.3-5.5V TSSOP8; AGILE_PN: 312-80889; CAD_APPROVED: Yes; HEIGHT: 1.1MM; MFG_NAME01: NXP SEMICONDUCTORS; MFG_PN01: NTS0102DP; ROHS: Yes
U46 U49 = 74LVCH1T45_6P: IC XCVR XLATING DUAL 3-STATE 1.2- 5.5V TSSOP6; AGILE_PN: 312-81277; CAD_APPROVED: Yes; HEIGHT: 1.1MM; MFG_NAME01: NEXPERIA; ROHS: Yes
U48 = 74LVC2T45DC_8P: IC TRANSLATING XCVR DUAL BIT/SUPPLY TS 1.2-5.5V VSSOP8; AGILE_PN: 312-81751; CAD_APPROVED: Yes; HEIGHT: 1MM; MFG_NAME01: NEXPERIA; ROHS: Yes; Temp_Range: -40°C to +125°C
U50 = LPC432_BGA_100P: IC MCU  CORTEX M4 CORE 512kB FLASH 2.4-3.6V BGA100; AGILE_PN: 344-02176; CAD_APPROVED: Yes; HEIGHT: 1.2MM; MFG_NAME01: NXP SEMICONDUCTORS; MFG_PN01: LPC4322JET100E; ROHS: Yes
Y5 = XTAL: XTAL 12MHZ RSN -- 18PF 30PPM SMT; AGILE_PN: 230-78082; CAD_APPROVED: Yes; HEIGHT: 3.3MM; MFG_NAME01: ABRACON CORP; MFG_PN01: ABLS2-12.000MHZ-D4Y-T; ROHS: Yes
R253-R264 = RES: RES MF 47K  1/16W 1% 0402; AGILE_PN: 470-31023; CAD_APPROVED: Yes; FPLIST: RC0402_25,RC0402_HD,0402_CC; HEIGHT: 0.40 MM; MFG_NAME01: YAGEO AMERICA; MFG_PN01: RC0402FR-0747KL; ROHS: Yes; Tolerance: 1%
R270 = RES: RES MF 1.0K 1/16W 5% 0402; AGILE_PN: 470-75555; ASSY_OPT: DNP; CAD_APPROVED: Yes; FPLIST: RC0402_25,RC0402_HD,RC0402_X2,0402_CC; HEIGHT: 0.41mm; MFG_NAME01: VISHAY INTERTECHNOLOGY; MFG_PN01: CRCW04021K00JNED; ROHS: Yes; Tolerance: 5%
SW8 = SW_DIP4: SW DIP 4 POS 0.025A@24VDC SMT; AGILE_PN: 510-78047; CAD_APPROVED: Yes; HEIGHT: 2.1MM; MFG_NAME01: WURTH ELEKTRONIK EISOS GMBH & CO. KG; ROHS: Yes
C280 C281 = CAP_NP: CAP CER 220PF 50V 5% C0G 0402; AGILE_PN: 150-30297; CAD_APPROVED: Yes; FPLIST: CC0402_25,CC0402_HD,0402_CC; HEIGHT: 0.55MM; MFG_NAME01: KEMET; MFG_PN01: C0402C221J5GAC; ROHS: Yes; Tolerance: 5%; VOLTAGE: 50V
R2 R6 = RES: RES MF 100 OHM 1/16W 1% 0402; AGILE_PN: 470-30454; CAD_APPROVED: Yes; FPLIST: RC0402_25,RC0402_HD,0402_CC; HEIGHT: 0.4 MM; MFG_NAME01: THYE MING TECH CO LTD; MFG_PN01: CR-02FL6--100R; ROHS: Yes; TOL: 1%; Tolerance: 1%
R8 R9 = RES: RES MF 4.99K 1/16W 1% 0402; AGILE_PN: 470-81149; CAD_APPROVED: Yes; FPLIST: RC0402_25,RC0402_HD,0402_CC; HEIGHT: 0.4 MM; MFG_NAME01: YAGEO AMERICA; MFG_PN01: RC0402FR-074K99L; ROHS: Yes; Tolerance: 1%
R249 R250 = RES: RES MF 4.7K 1/16W 5% 0402; AGILE_PN: 470-75626; ASSY_OPT: DNP; CAD_APPROVED: Yes; FPLIST: RC0402_25,RC0402_HD,0402_CC; HEIGHT: 0.41mm; MFG_NAME01: NIC COMPONENTS CORP; MFG_PN01: NRCL04J472TRF; ROHS: Yes; Tolerance: 5%
U26 = FXOS8700CQ_QFN_16P: IC ACCELEROMETER AND MAGNETOMETER SENSOR 3-AXIS 2.5V QFN16; AGILE_PN: 312-80418; ASSY_OPT: DNP; CAD_APPROVED: Yes; FPLIST: QFN5X3_0P5_3X3,QFN5X3_0P5_3X3_a; HEIGHT: 1.25MM; MFG_NAME01: Freescale Semiconductor; ROHS: Yes
U27 = MX25L6406EM2I_SOP8: IC MEM FLASH SPI 4MBIT 86MHZ 2.7-3.6V AUTOMOTIVE SOP8; AGILE_PN: 334-77823; ASSY_OPT: DNP; CAD_APPROVED: Yes; HEIGHT: 2.16MM; MFG_NAME01: MACRONIX INTERNATIONAL CO., LTD; ROHS: Yes; Temp_Range: -40°C ~ 105°C

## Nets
5V_SDA_PSW: C241.1 R352.1 U31.C2(VBUS1) U31.D1(VBUS2) U31.D2(VBUS3)
5V_SYS: D14.A J20.8 ; also on sheet 4 7 8
GND: C142.2 C143.2 C167.2 C168.2 C169.2 C170.2 C184.2 C185.2 C186.2 C241.2 C254.2 C255.2 C257.2 C258.2 C259.2 C260.2 C261.2 C262.2 C263.2 C264.2 C265.2 C266.2 C267.2 C268.2 C270.2 C272.2 C273.2 C274.2 C275.2 C276.2 C277.2 C278.2 C280.2 C281.2 C285.2 C314.2 C315.2 D20.C(CATHODE) J19.7 J20.6 J20.7 J29.2 J30.2 J34.3(A2) J34.5(A3) J41.5(P5) J42.1 J55.3(A2) J55.5(A3) L21.2 R9.2 R214.2 R244.2 R246.2 R248.2 R253.1 R254.1 R255.1 R256.1 R257.1 R258.1 R259.1 R260.1 R261.1 R262.1 R263.1 R264.1 R351.2 R377.2 R380.1 R387.1 R389.2 R391.2 R414.2 SW9.1(A1) SW9.2(A2) U13.4(GND) U26.3(RSVD1) U26.5(GND1) U26.12(GND2) U26.13(RSVD2) U27.4(GND) U31.B3(GND1) U31.C3(GND2) U31.D3(GND3) U39.1(GND) U40.2(GND) U44.4(GND) U45.2(GND) U46.2(GND) U48.4(GND) U49.2(GND) U49.5(DIR) U50.C2(VSSA) U50.C8(VSS1) U50.D3(USB0_VSSA_TERM) U50.D4(VSS2) U50.D5(VSS3) U50.F2(USB0_VSSA_REF) U50.G8(VSS4) U50.J3(VSS5) U50.J6(VSS6) ; also on sheet 1 4 5 6 7 8
P3V3_SDA: C186.1 C255.1 C260.1 C262.1 C263.1 C264.1 C265.1 C266.1 C267.1 C270.1 J34.1(A1) L22.1 R213.1 R215.1 R378.1 R381.1 R382.1 R383.1 R388.2 R390.2 R394.1 R402.2 R413.1 R418.2 R423.1 U40.5(OUT) U44.1(VCCA) U45.3(VCCA) U46.1(VCCA) U48.1(VCCA) U49.1(VCCA) U50.B2(VDDA) U50.C5(VBAT) U50.D1(USB0_VDDA3V3_DRIVER) U50.D2(USB0_VDDA3V3) U50.F10(VDDIO1) U50.K5(VDDIO2)
P5V0_SDA_USB_CONN_VBUS: J41.1(P1) L23.1 U39.4(VCC)
P5V_SDA: C184.1 C185.1 C257.1 C259.1 L23.2 R212.1 R353.1 R379.1 U31.B1(VINT1) U31.B2(VINT2) U31.C1(VINT3) U40.1(IN) U40.3(~{SHDN})
P5V_SDA_S: R352.2 R353.2 ; also on sheet 4
ADC12_1: C280.1 R2.2 R158.2 ; also on sheet 6
ADC12_2: C281.1 R6.2 R166.2 ; also on sheet 6
ARM_TRACE_SWO: J50.2 J55.6(B3) ; also on sheet 6
BOOT0_LED: R388.1 R392.1 U50.K2(P1_1/GPIO0[8]/CTOUT_7/EMC_A6/SGPIO8/SSP0_MISO/EMC_D13)
BOOT1: R389.1 U50.K1(P1_2/GPIO0[9]/CTOUT_6/EMC_A7/SGPIO9/SSP0_MOSI/EMC_D14)
BOOT2: R390.1 U50.C6(P2_8/SGPIO15/CTOUT_0/U3_DIR/EMC_A8/GPIO5[7])
BOOT3: R391.1 U50.B10(P2_9/GPIO1[10]/CTOUT_3/U3_BAUD/EMC_A0)
BOOT_FLASH: J42.2 U50.C10(P2_7/GPIO0[7]/CTOUT_1/U3_UCLK/EMC_A9/T3_MAT3)
DCDC_3V3: C268.1 C275.1 C276.1 C277.1 C278.1 C285.1 C314.1 C315.1 J19.8 J20.2 J20.4 J55.1(A1) R142.1 R239.1 R265.1 R266.1 R267.1 R268.1 R270.1 R393.1 R401.1 R411.1 R412.1 R419.2 R422.2 R436.1 R437.1 R440.1 R441.1 R778.1 U44.8(VCCB) U45.7(VCCB) U46.6(VCCB) U48.8(VCCB) U49.6(VCCB) ; also on sheet 1 4 5 6 7 8
FLASH_3V3: C142.1 C143.1 R142.2 R143.1 R313.1 R438.1 U13.8(VCC)
FlexSPI_CLK_A: U13.6(SCLK) ; also on sheet 6
FlexSPI_D0_A: U13.5(SI/IO0) ; also on sheet 6
FlexSPI_D1_A: U13.2(SO/IO1) ; also on sheet 6
FlexSPI_D2_A: R438.2 U13.3(~{WP}/IO2) ; also on sheet 6
FlexSPI_D3_A: R313.2 U13.7(~{HOLD}/IO3) ; also on sheet 6
FlexSPI_SS0: R143.2 U13.1(~{CS}) ; also on sheet 6
GPIO_AD_B0_05: J55.10(B5) R437.2 ; also on sheet 6
GPIO_AD_B0_10: R172.2 R439.1 ; also on sheet 6
GPIO_AD_B0_11: R169.2 R443.1 ; also on sheet 6
GPIO_AD_B0_12: R170.2 R442.1 ; also on sheet 6
GPIO_AD_B0_13: R171.2 R444.1 ; also on sheet 6
GPIO_AD_B1_10: R161.2 ; also on sheet 6 7
GPIO_AD_B1_11: R164.2 ; also on sheet 6 7
GPIO_AD_B1_12: R159.2 ; also on sheet 6 7
GPIO_AD_B1_13: R157.2 ; also on sheet 6
GPIO_AD_B1_14: R165.2 R174.2 R249.2 R251.2 ; also on sheet 6 8
GPIO_AD_B1_15: R163.2 R173.2 R250.2 R252.2 ; also on sheet 6 8
GPIO_EMC_16: R254.2 SW8.4(A4) ; also on sheet 6
GPIO_EMC_17: R253.2 SW8.3(A3) ; also on sheet 6
GPIO_EMC_18: R264.2 SW8.1(A1) ; also on sheet 6 8
GPIO_EMC_19: R263.2 ; also on sheet 6 8
GPIO_EMC_20: R155.2 R262.2 ; also on sheet 6 8
GPIO_EMC_21: R167.2 R261.2 ; also on sheet 6 8
GPIO_EMC_22: R168.2 R260.2 ; also on sheet 6 8
GPIO_EMC_23: R259.2 ; also on sheet 6 8
GPIO_EMC_24: R258.2 R782.2 ; also on sheet 6 8
GPIO_EMC_25: R257.2 R783.2 ; also on sheet 6 8
GPIO_EMC_26: R156.2 R256.2 R270.2 ; also on sheet 6 8
GPIO_EMC_27: R162.2 R255.2 SW8.2(A2) ; also on sheet 6 8
GPIO_EMC_32: J29.3 R154.2 ; also on sheet 6
GPIO_EMC_33: J29.1 R153.2 ; also on sheet 6
GPIO_EMC_34: R160.2 ; also on sheet 6
GPIO_EMC_35: R784.2 ; also on sheet 6
INT1_COMBO: R241.2 R242.2 ; also on sheet 6
INT2_COMBO: R240.2 R243.2 ; also on sheet 6
JTAG_RESET: J44.2 U50.D10(P2_5/SGPIO14/CTIN_2/USB1_VBUS/ADCTRIG1/GPIO5[5]/T3_MAT2/USB0_IND0)
JTAG_TCK: J48.2 J55.4(B2) ; also on sheet 6
JTAG_TDI: J49.2 J55.8(B4) ; also on sheet 4 6
JTAG_TDI_L: U48.3(2A) U50.J10(P1_18/GPIO0[13]/U2_DIR/ENET_TXD0/T0_MAT3/CAN1_RD/SGPIO12/EMC_D10)
JTAG_TDI_TGTMCU_BUF: J49.1 R417.2
JTAG_TDO_TGTMCU_BUF: J50.1 R422.1 U49.4(B)
JTAG_TMS: J47.2 J55.2(B1) R436.2 ; also on sheet 6
LPUART1_RXD: J45.2 R411.2 ; also on sheet 6
LPUART1_TXD: J46.2 R393.2 ; also on sheet 6
LPUART3_RX: J30.1 ; also on sheet 6
LPUART3_TX: J30.3 ; also on sheet 6
POR_B: D21.C(CATHODE) J21.1 J43.3 R401.2 R410.2 U44.7(B1) ; also on sheet 5
POWER_EN: R216.1 U50.F7(P3_1/I2S0_TX_WS/I2S0_RX_WS/CAN0_RD/USB1_IND1/GPIO5[8]/LCD_VD15)
SDA_JTAG_TCLK: J34.4(B2) U50.H2(TCK/SWDCLK)
SDA_JTAG_TDI: J34.8(B4) U50.G3(TDI)
SDA_JTAG_TDO: J34.6(B3) U50.H3(TDO/SWO)
SDA_JTAG_TMS: J34.2(B1) R213.2 U50.C4(TMS/SWDIO)
SDA_RST: J34.10(B5) R423.2 U50.B4(~{TRST})
SDA_RST_LED: D21.A(ANODE) R412.2
SDA_RST_TGTMCU_J_B: J44.1 R400.1 R410.1
SDA_USB_CONN_DM: J41.2(P2) R375.1 U39.2(I/O1)
SDA_USB_CONN_DP: J41.3(P3) R376.1 U39.3(I/O2)
SDA_USB_DM: R375.2 U50.E2(USB0_DM)
SDA_USB_DP: R376.2 U50.E1(USB0_DP)
SDA_USBSHIELD: J41.S1(SHLD1) J41.S2(SHLD2) J41.S3(SHLD3) J41.S4(SHLD4) L21.1
SENSOR_3V3: C167.1 C168.1 R8.1 R239.2 R240.1 R241.1 R245.1 R247.1 R249.1 R250.1 U26.1(VDDIO) U26.14(VDD)
SW1_RST_B: C272.1 J43.2 SW9.3(B1) SW9.4(B2)
SWD_CLK_TGTMCU_BUF: J48.1 R416.2
SWD_DIO_TGTMCU_BUF: J47.1 R419.1 U46.4(B)
TC_SDA_USB_ID: J41.4(P4) U50.F1(USB0_ID)
TCK_SWCLK: U48.2(1A) U50.H10(P1_17/GPIO0[12]/U2_UCLK/ENET_MDIO/T0_CAP3/CAN1_TD/SGPIO11)
TDO_SWO: U49.3(A) U50.J8(P1_14/GPIO1[7]/U1_RXD/EMC_D7/T0_MAT2/SGPIO10)
TMS_SWDIO: U46.3(A) U50.K4(P1_6/GPIO1[9]/CTIN_5/~{EMC_WE}/~{EMC_BLS0}/SGPIO14/SD_CMD)
TMS_SWDIO_TXEN: R414.1 U46.5(DIR) U50.J4(P1_5/GPIO1[8]/CTOUT_10/~{EMC_CS0}/USB0_PWR_FAULT/SSP1_SSEL/SGPIO15/SD_POW)
TP_2102_A: TP29.1(Pin1) U44.3(A2)
TP_2102_B: TP30.1(Pin1) U44.6(B2)
UART1_RX_TGTMCU_BUF: J45.1 U45.8(B1)
UART1_TX_TGTMCU_BUF: J46.1 U45.1(B2)
UART_RXD_ISP: U45.5(A1) U50.G10(P2_0/SGPIO4/U0_TXD/EMC_A13/USB0_PPWR/GPIO5[0]/T3_CAP0/ENET_MDC)
UART_TXD_ISP: U45.4(A2) U50.G7(P2_1/SGPIO5/U0_RXD/EMC_A12/USB0_PWR_FAULT/GPIO5[1]/T3_CAP1)
VTRG_FAULT_B: R215.2 U31.A2(~{FAULT}) U50.A8(P3_0/I2S0_RX_SCK/I2S0_RX_MCLK/I2S0_TX_SCK/I2S0_TX_MCLK/SSP0_SCK)
N99909350: R247.2 R248.1 U26.7(SA0/MISO)
N99909356: R244.1 U26.16(RST)
N99909379: R252.1 U26.6(SDA/MOSI)
N99909383: R251.1 U26.4(SCL/SCLK)
N99909400: C170.1 U26.2(BYP)
N99909418: C169.1 U26.8(CRST)
N99909466: R243.1 U26.9(INT2)
N99909468: R242.1 U26.11(INT1)
N99909488: R245.2 R246.1 U26.10(SA1/~{CS})
N99916564: J18.5 R163.1
N99916634: J18.6 R165.1
N99916953: J20.3 J21.2
N99916957: D14.C J20.5
N99917118: J19.9 R173.1
N100226419: R266.2 SW8.6(B3)
N100226426: R267.2 SW8.7(B2)
N100226433: R268.2 SW8.8(B1)
N100640762: J19.10 R174.1
N100784802: J18.1 R157.1
N100784828: J18.2 R158.1
N100784935: J18.3 R159.1
N100784954: J18.4 R161.1
N101471655: J19.1 R167.1
N101471657: J19.2 R168.1
N101471661: J19.3 R169.1 R782.1
N101471663: J19.5 R171.1
N101505077: J17.5 R160.1
N101505079: J17.3 R155.1
N101505081: J17.6 R162.1 R784.1
N101505083: J17.8 R166.1
N101505085: J17.7 R164.1
N101505087: J17.4 R156.1
N101505091: J17.1 R153.1
N101583028: R265.2 SW8.5(B4)
N101646424: D20.A(ANODE) R392.2
N101646485: R387.2 U50.C9(P6_11/GPIO3[7]/EMC_CKEOUT0/T2_MAT3)
N101647261: R351.1 U31.A3(ILIM)
N101647280: R212.2 R214.1 R216.2 U31.A1(EN)
N101652174: J43.1 R394.2 R400.2 U44.2(A1)
N101652379: R402.1 U44.5(OE)
N101652682: R413.2 U45.6(OE)
N101652838: R416.1 U48.7(1B)
N101652851: R417.1 U48.6(2B)
N101652913: R418.1 U48.5(DIR)
N101655535: R377.1 R378.2 U40.4(FB)
N101655576: R379.2 U50.E3(USB0_VBUS)
N101655591: R380.2 U50.F3(USB0_RREF)
N101655607: C254.1 C258.1 C261.1 L22.2 U50.E4(VDDREG1) U50.E5(VDDREG2) U50.F4(VDDREG3)
N101655735: R381.2 U50.A6(DBGEN)
N101655737: R382.2 U50.B6(~{RESET})
N101655752: R383.2 U50.A4(WAKEUP0)
N101655907: C274.1 U50.B1(XTAL1) Y5.1
N101656203: C273.1 U50.C1(XTAL2) Y5.2
N101743321: C282.1 R2.1 R8.2 R432.1
N101743332: C282.2 R6.1 R9.1 R432.2
N101775714: J19.6 R172.1
N101776433: J19.4 R170.1 R783.1
N101777070: J17.2 R154.1
N101792743: R777.1 R778.2 U27.8(VCC)
N101792747: R777.2 U27.7(~{HOLD})
N101792774: R439.2 U27.6(SCLK)
N101792783: R442.2 U27.5(SI/SIO0)
N101792788: R440.2 U27.3(~{WP})
N101792823: R441.2 R443.2 U27.1(~{CS})
N101792856: R444.2 U27.2(SO/SIO1)

Not connected (* = marked no-connect by the designer): J20 1*; J34 7(A4)* 9(A5)*; J55 7(A4)* 9(A5)*; U26 15(NC)*; U50 A1(ADC0_1/ADC1_1)* A2(ADC0_0/ADC1_0/DAC)* A3(ADC0_3/ADC1_3)* A5(RTCX1)* A7(P3_3/SPI_SCK/SSP0_SCK/SPIFI_SCK/CGU_OUT1/I2S0_TX_MCLK/I2S1_TX_SCK)* A9(P2_11/GPIO1[11]/CTOUT_5/U2_RXD/EMC_A2)* A10(P2_13/GPIO1[13]/CTIN_4/EMC_A4/U2_DIR)* B3(ADC0_2/ADC1_2)* B5(RTCX2)* B7(P3_5/GPIO1[15]/SPIFI_SIO2/U1_RXD/I2S0_TX_SDA/I2S1_RX_WS/LCD_VD12)* B8(P3_4/GPIO1[14]/SPIFI_SIO3/U1_TXD/I2S0_TX_WS/I2S1_RX_SDA/LCD_VD13)* B9(P2_12/GPIO1[12]/CTOUT_4/EMC_A3/U2_UCLK)* C3(RTC_ALARM)* C7(P3_6/GPIO0[6]/SPI_MISO/SSP0_SSEL/SPIFI_MISO/SSP0_MISO)* D6(I2C0_SCL)* D7(P3_7/SPI_MOSI/SSP0_MISO/SPIFI_MOSI/GPIO5[10]/SSP0_MOSI)* D8(P2_3/SGPIO12/I2C1_SDA/U3_TXD/CTIN_1/GPIO5[3]/T3_MAT0/USB0_PPWR)* D9(P2_4/SGPIO13/I2C1_SCL/U3_RXD/CTIN_0/GPIO5[4]/T3_MAT1/USB0_PWR_FAULT)* E6(I2C0_SDA)* E7(P3_8/SPI_SSEL/SSP0_MOSI/SPIFI_CS/GPIO5[11]/SSP0_SSEL)* E8(P2_10/GPIO0[14]/CTOUT_2/U2_TXD/EMC_A1)* E9(USB1_DP)* E10(USB1_DM)* F5(P2_2/SGPIO6/U0_UCLK/EMC_A11/USB0_IND1/GPIO5[2]/CTIN_6/T3_CAP2/~{EMC_CS1})* F6(P6_4/GPIO3[3]/CTIN_6/U0_TXD/~{EMC_CAS})* F8(P6_9/GPIO3[5]/~{EMC_DYCS0}/T2_MAT2)* F9(P6_5/GPIO3[4]/CTOUT_6/U0_RXD/~{EMC_RAS})* G1(P0_1/GPIO0[1]/SSP1_MOSI/ENET_COL/SGPIO1/ENET_TX_EN/I2S1_TX_SDA)* G2(P0_0/GPIO0[0]/SSP1_MISO/ENET_RXD1/SGPIO0/I2S0_TX_WS/I2S1_TX_WS)* G4(P1_7/GPIO1[0]/U1_DSR/CTOUT_13/EMC_D0/USB0_PPWR)* G5(P6_1/GPIO3[0]/~{EMC_DYCS1}/U0_UCLK/I2S0_RX_WS/T2_CAP0)* G6(P3_2/I2S0_TX_SDA/I2S0_RX_SDA/CAN0_TD/USB1_IND0/GPIO5[9]/LCD_VD14)* G9(P2_6/SGPIO7/U0_DIR/EMC_A10/USB0_IND0/GPIO5[6]/CTIN_7/T3_CAP3/~{EMC_BLS1}) H1(P1_0/GPIO0[4]/CTIN_3/EMC_A5/SSP0_SSEL/SGPIO7/EMC_D12)* H4(PF_4/SSP1_SCK/GP_CLKIN/TRACECLK/I2S0_TX_MCLK/I2S0_RX_SCK)* H5(P1_8/GPIO1[1]/U1_DTR/CTOUT_12/EMC_D1/SD_VOLT0)* H6(P1_10/GPIO1[3]/U1_RI/CTOUT_14/EMC_D3/SD_DAT1)* H7(P6_0/I2S0_RX_MCLK/I2S0_RX_SCK)* H8(P1_13/GPIO1[6]/U1_TXD/EMC_D6/T0_CAP0/SGPIO9/SD_CD)* H9(P1_16/GPIO0[3]/U2_RXD/SGPIO3/ENET_CRS/T0_MAT0/EMC_D9/ENET_RX_DV)* J1(P1_3/GPIO0[10]/CTOUT_8/SGPIO10/~{EMC_OE}/USB0_IND1/SSP1_MISO/SD_RST)* J2(P1_4/GPIO0[11]/CTOUT_9/SGPIO11/~{EMC_BLS0}/USB0_IND0/SSP1_MOSI/EMC_D15/SD_VOLT1)* J5(P1_9/GPIO1[2]/U1_RTS/CTOUT_11/EMC_D2/SD_DAT0)* J7(P1_11/GPIO1[4]/U1_CTS/CTOUT_15/EMC_D4/SD_DAT2)* J9(P6_2/GPIO3[1]/EMC_CKEOUT1/U0_DIR/I2S0_RX_SDA/T2_CAP1)* K3(CLK0/EMC_CLK0/CLKOUT/SD_CLK/EMC_CLK01/SSP1_SCK/ENET_TX_CLK/ENET_REF_CLK)* K6(CLK2/EMC_CLK3/CLKOUT/SD_CLK/EMC_CLK23/I2S0_TX_MCLK/I2S1_RX_SCK)* K7(P1_12/GPIO1[5]/U1_DCD/EMC_D5/T0_CAP1/SGPIO8/SD_DAT3)* K8(P1_15/GPIO0[2]/U2_TXD/SGPIO2/ENET_RXD0/T0_MAT1/EMC_D8)* K9(P1_19/ENET_TX_CLK/ENET_REF_CLK/SSP1_SCK/CLKOUT/I2S0_RX_MCLK/I2S1_TX_SCK)* K10(P1_20/GPIO0[15]/SSP1_SSEL/ENET_TXD1/T0_CAP2/SGPIO13/EMC_D11)*

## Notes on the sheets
sheet 9
- 3v3 QSPI Flash
sheet 10
- Freelink Interface
- Vfb=1V
- Short (JP42) to force
  DFU Boot Mode
- JTAG CONNECTOR
- RESET
- 1-2: Default.
  2-3: Reset signal direct to the MCU,
  to use when OpenSDA is not powered.
- RST Push Button
  Bypass
- TARGET MCU
  INTERFACE
  SIGNALS
- RST_TGTMCU_B
- PWR SWITCH
- (To enable 5V from
   USB connector)
- UART1_RX_TGTMCU
- Isolation
  Jumpers
- MAX 500 mA @5V
- UART1_TX_TGTMCU
- SWD_DIO_TGTMCU
- SWD_CLK_TGTMCU
- JTAG_TDI_TGTMCU
- JTAG_TDO_TGTMCU
sheet 11
- Serial Downloader: 0001
       FlexSPI Boot: 0010
sheet 12
- COMBO SENSOR
- I2C SLAVE ADDRESS = 0X1F
- ADC Sampling
- INT1_COMBO
- INT2_COMBO
- CRST_FXOS8700CQ
- RST_FXOS8700CQ
- BYP_FXOS8700CQ
- CLOSE TO CHIP
- SA1_FXOS8700CQ
- SA0_FXOS8700CQ
- I2C_SCL_FXOS8700CQ
- I2C_SDA_FXOS8700CQ
- FXOS8700CQ COMBO SENSOR
- LPSPI Flash
sheet 13
- JTAG Connector
- Arduino Interface
- D0/UART_RX
- GPIO_EMC_33
- D1/UART_TX
- GPIO_EMC_32
- A0/ADC0
- GPIO_AD_B1_13
- D2/INT0
- D3/INT1/PWM/OC2B
- GPIO_EMC_20
- GPIO_EMC_26
- A1/ADC1
- A2/ADC2
- GPIO_AD_B0_14
- GPIO_AD_B1_12
- D4/T0/XCK
- GPIO_EMC_34
- A3/ADC3
- GPIO_AD_B1_10
- D5/TI/PWM
- GPIO_EMC_27
- A4/ADC4/SDA
- GPIO_AD_B1_15
- D6/AIN0/PWM/OC0A
- GPIO_AD_B1_11
- A5/ADC5/SCL
- GPIO_AD_B1_14
- D7/AIN1
- GPIO_AD_B0_15
- D8/CLKO/ICP1
- GPIO_EMC_21
- D10/SPI_CS/PWM
- D9/OC1A/PWM
- GPIO_AD_B0_11
- GPIO_EMC_22
- IOREF
- D11/OC2A/PWM/SPI_MOSI
- GPIO_AD_B0_12
- RESET_b
- POR_B
- D12/SPI_MISO
- GPIO_AD_B0_13
- 3V3
- D13/SPI_CLK
- GPIO_AD_B0_10
- 5V
- GPIO_AD_B1_15
- AREF
- GPIO_AD_B1_14
- D14/I2C_SDA
- D15/I2C_SCL
- VIN
